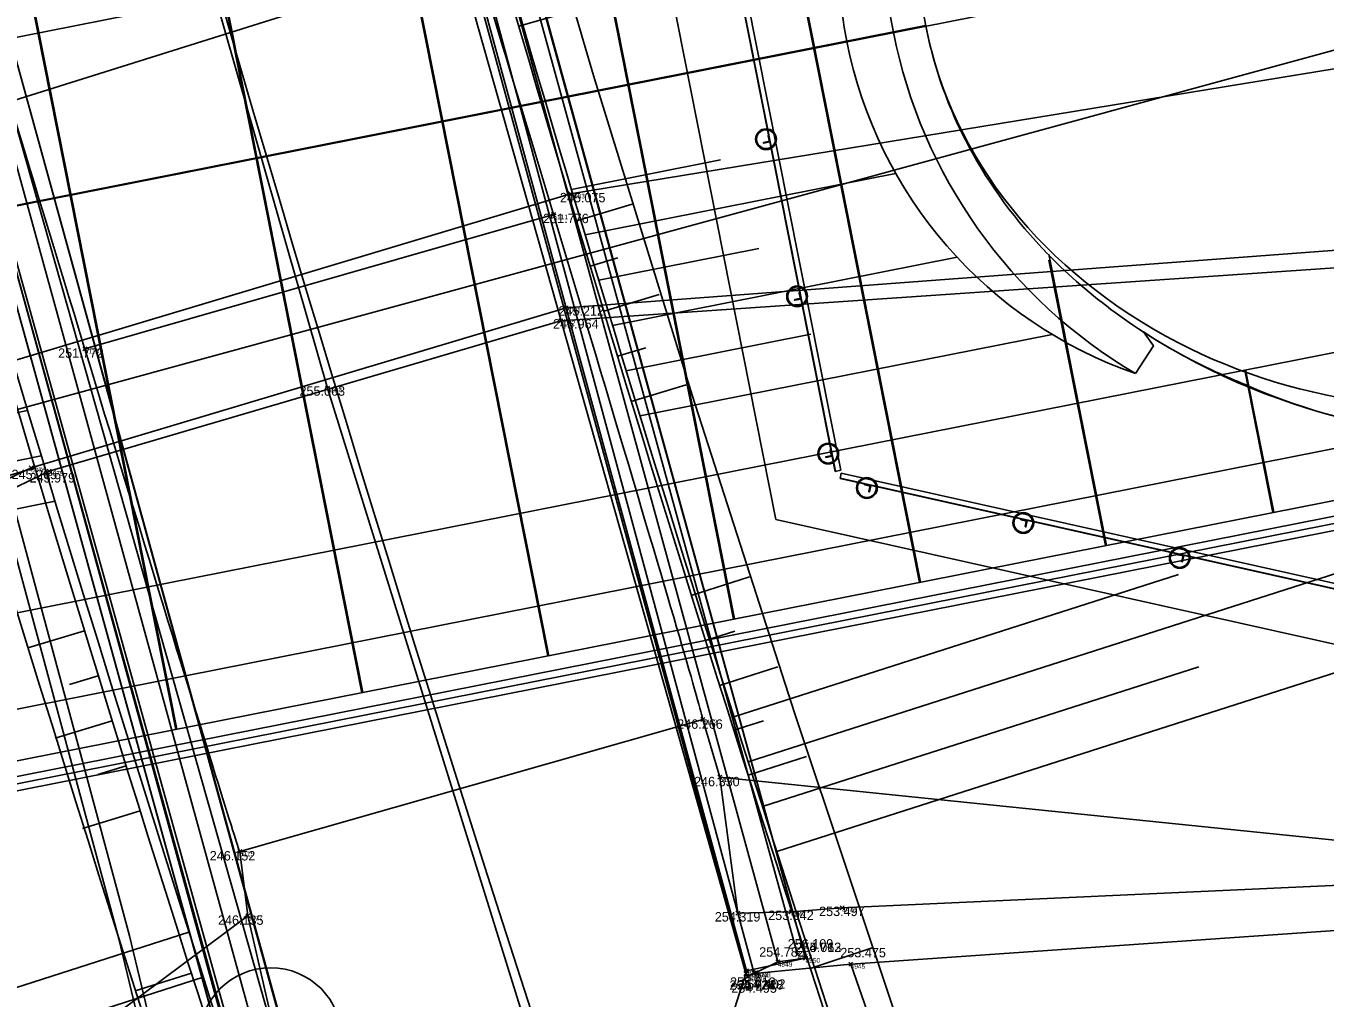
# Model space of a CAD drawing. Extents: x -809973 to -809318, y -1011363 to -1010505.
# Drawn here: x -809841.74 to -809827.96, y -1010996.1 to -1010985.79 of the extents above; entities that cross this region are included whole.
import ezdxf

# ---------------------------------------------------------------- set-up
doc = ezdxf.new("R2010")
doc.units = 0
for name, color, linetype in [('18b - zaměření - čísla bodů', 7, 'Continuous'), ('18c - zaměření - výšky', 7, 'Continuous'), ('21 - sítě', 7, 'Continuous'), ('21a - sítě - DKK - ČD Telematika a.s.', 7, 'Continuous'), ('21b - sítě - SŽDC - SSZT', 7, 'Continuous'), ('21d - sítě - obnova rybníku a obnova náhonu pro rybník', 7, 'Continuous'), ('Návrh', 7, 'Continuous'), ('SO04 - Železniční spodek', 7, 'Continuous'), ('SO05 - Úprava kabelů', 7, 'Continuous'), ('SO_01', 7, 'Continuous'), ('stav_stav', 7, 'Continuous')]:
    doc.layers.add(name, color=color, linetype=linetype)

# ---------------------------------------------------------------- blocks, each defined once
blk = doc.blocks.new('POINT_DISPLAY')
for p, q in [((-0.021, -0.021), (0.021, 0.021)), ((-0.021, 0.021), (0.021, -0.021))]:
    blk.add_line(p, q)

msp = doc.modelspace()

# ---------------------------------------------------------------- linework, layer by layer
at = {"layer": '21 - sítě'}
msp.add_lwpolyline([(-809832.875, -1011017.263), (-809833.494, -1011015.746), (-809838.391, -1011005.426), (-809840.703, -1011001.729), (-809840.806, -1011000.123), (-809839.446, -1010997.434), (-809844.081, -1010980.644), (-809845.074, -1010978.711), (-809846.471, -1010977.412)], dxfattribs=at)
at = {"layer": '21a - sítě - DKK - ČD Telematika a.s.'}
msp.add_lwpolyline([(-809840.802, -1011000.183), (-809839.446, -1010997.434), (-809844.081, -1010980.644), (-809845.074, -1010978.711), (-809846.471, -1010977.412)], dxfattribs=at)
at = {"layer": '21b - sítě - SŽDC - SSZT'}
msp.add_lwpolyline([(-809840.802, -1011000.183), (-809839.446, -1010997.434), (-809844.081, -1010980.644), (-809845.074, -1010978.711), (-809846.471, -1010977.412)], dxfattribs=at)
at = {"layer": '21d - sítě - obnova rybníku a obnova náhonu pro rybník'}
msp.add_lwpolyline([(-809884.652, -1011011.671), (-809852.391, -1010992.741), (-809838.71, -1010989.006), (-809826.649, -1010985.714), (-809807.016, -1010985.926), (-809784.688, -1010978.607)], dxfattribs=at)
at = {"layer": 'Návrh'}
msp.add_arc((-809483.868, -1010882.207), 370.5, 195.00213, 204.78693, dxfattribs=at)
at = {"layer": 'SO04 - Železniční spodek'}
for points in [[(-809844.502, -1010948.259), (-809843.86, -1010951.753), (-809843.202, -1010955.243), (-809842.522, -1010958.729), (-809841.813, -1010962.21), (-809841.069, -1010965.683), (-809840.285, -1010969.148), (-809839.459, -1010972.604), (-809838.59, -1010976.05), (-809837.678, -1010979.484), (-809836.721, -1010982.905), (-809835.72, -1010986.314), (-809834.673, -1010989.708), (-809833.585, -1010993.088), (-809832.46, -1010996.457), (-809831.306, -1010999.816), (-809830.127, -1011003.167), (-809828.93, -1011006.512), (-809827.721, -1011009.854), (-809826.507, -1011013.193)], [(-809835.954, -1010985.634), (-809836.514, -1010985.793)], [(-809835.312, -1010987.682), (-809835.9, -1010987.859)], [(-809835.461, -1010988.249), (-809835.756, -1010988.338)], [(-809835.025, -1010988.64), (-809835.611, -1010988.816)], [(-809835.167, -1010989.205), (-809835.466, -1010989.295)], [(-809834.739, -1010989.598), (-809835.32, -1010989.773)], [(-809842.264, -1010990.66), (-809841.644, -1010990.478)], [(-809834.065, -1010991.635), (-809834.683, -1010991.832)], [(-809841.721, -1010992.389), (-809841.12, -1010992.207)], [(-809834.222, -1010992.21), (-809834.533, -1010992.309)], [(-809833.764, -1010992.589), (-809834.383, -1010992.786)], [(-809841.278, -1010992.778), (-809840.973, -1010992.685)], [(-809841.431, -1010993.346), (-809840.826, -1010993.163)], [(-809833.918, -1010993.163), (-809834.232, -1010993.263)], [(-809833.462, -1010993.542), (-809834.081, -1010993.739)], [(-809840.978, -1010993.732), (-809840.678, -1010993.641)], [(-809841.141, -1010994.304), (-809840.529, -1010994.118)], [(-809832.765, -1010995.572), (-809833.421, -1010995.79)], [(-809840.582, -1010996.028), (-809839.985, -1010995.841)]]:
    msp.add_lwpolyline(points, dxfattribs=at)
for centre, radius, start, end in [((-809453.305, -1010872.818), 406.4, 193.63597, 201.43276), ((-809483.922, -1010882.181), 367.5, 195.00277, 200.92799), ((-809524.411, -1010895.31), 331.2, 194.62152, 202.36706)]:
    msp.add_arc(centre, radius, start, end, dxfattribs=at)
at = {"layer": 'SO05 - Úprava kabelů'}
for points in [[(-809832.452, -1011018.3), (-809834.599, -1011012.541), (-809836.558, -1011007.657), (-809839.63, -1011000.177), (-809840.754, -1010995.474), (-809845.885, -1010976.431), (-809847.466, -1010970.457), (-809849.998, -1010958.97), (-809853.746, -1010939.574), (-809862.448, -1010886.367), (-809861.681, -1010881.903), (-809870.184, -1010824.906)], [(-809832.343, -1011018.259), (-809834.49, -1011012.499), (-809836.45, -1011007.613), (-809839.519, -1011000.141), (-809840.641, -1010995.445), (-809845.773, -1010976.401), (-809847.353, -1010970.429), (-809849.884, -1010958.947), (-809853.631, -1010939.554), (-809862.33, -1010886.367), (-809861.563, -1010881.905), (-809870.069, -1010824.889)]]:
    msp.add_lwpolyline(points, dxfattribs=at)
at = {"layer": 'SO_01'}
for p, q in [((-809834.505, -1010980.356), (-809832.262, -1010991.694)), ((-809834.495, -1010980.354), (-809832.252, -1010991.692)), ((-809836.477, -1010980.746), (-809834.234, -1010992.084)), ((-809836.467, -1010980.744), (-809834.224, -1010992.082)), ((-809838.448, -1010981.136), (-809836.206, -1010992.474)), ((-809838.439, -1010981.134), (-809836.196, -1010992.472)), ((-809840.42, -1010981.526), (-809838.178, -1010992.864)), ((-809840.41, -1010981.524), (-809838.168, -1010992.862)), ((-809833.153, -1010990.515), (-809834.88, -1010981.784)), ((-809833.099, -1010990.504), (-809834.826, -1010981.774)), ((-809842.392, -1010981.916), (-809840.149, -1010993.254)), ((-809842.382, -1010981.914), (-809840.14, -1010993.252)), ((-809833.158, -1010990.516), (-809834.885, -1010981.785)), ((-809830.791, -1010985.512), (-809846.92, -1010988.702)), ((-809832.198, -1010985.784), (-809846.393, -1010988.591)), ((-809835.954, -1010987.524), (-809834.372, -1010987.211)), ((-809835.81, -1010988.005), (-809832.516, -1010987.354)), ((-809835.665, -1010988.486), (-809833.967, -1010988.15)), ((-809835.519, -1010988.967), (-809831.864, -1010988.244)), ((-809830.892, -1010988.212), (-809830.281, -1010991.302)), ((-809830.89, -1010988.274), (-809830.29, -1010991.304)), ((-809825.262, -1010988.739), (-809851.681, -1010993.965)), ((-809835.373, -1010989.448), (-809833.417, -1010989.061)), ((-809835.226, -1010989.928), (-809830.855, -1010989.064)), ((-809828.515, -1010990.952), (-809828.814, -1010989.442)), ((-809828.505, -1010990.95), (-809828.804, -1010989.44)), ((-809825.951, -1010989.895), (-809851.487, -1010994.946)), ((-809841.723, -1010989.871), (-809843.735, -1010990.269)), ((-809824.964, -1010990.25), (-809851.382, -1010995.475)), ((-809841.578, -1010990.352), (-809845.847, -1010991.197)), ((-809834.081, -1010993.596), (-809824.691, -1010990.588)), ((-809833.158, -1010990.516), (-809833.099, -1010990.504)), ((-809833.093, -1010990.534), (-809833.106, -1010990.592)), ((-809825.884, -1010992.206), (-809833.106, -1010990.592)), ((-809825.883, -1010992.202), (-809833.105, -1010990.588)), ((-809825.871, -1010992.148), (-809833.093, -1010990.534)), ((-809841.432, -1010990.833), (-809843.835, -1010991.308)), ((-809827.49, -1010990.916), (-809849.805, -1010995.33)), ((-809827.475, -1010990.99), (-809849.791, -1010995.404)), ((-809827.46, -1010991.063), (-809849.776, -1010995.477)), ((-809834.232, -1010993.119), (-809829.517, -1010991.609)), ((-809833.776, -1010994.548), (-809824.572, -1010991.6)), ((-809833.929, -1010994.072), (-809829.301, -1010992.59)), ((-809840.011, -1010995.405), (-809845.671, -1010997.224)), ((-809839.859, -1010995.881), (-809851.084, -1010999.488))]:
    msp.add_line(p, q, dxfattribs=at)
for points in [[(-809824.741, -1010990.164), (-809824.472, -1010992.461), (-809826.009, -1010992.763), (-809833.786, -1010991.025), (-809835.659, -1010981.554)], [(-809854.161, -1010988.344), (-809830.022, -1010983.57)], [(-809833.919, -1010987.03), (-809833.918, -1010987.032), (-809833.849, -1010987.019)], [(-809833.867, -1010987.015), (-809833.915, -1010987.025)], [(-809833.869, -1010986.956), (-809833.859, -1010987.005)], [(-809833.849, -1010987.019), (-809833.863, -1010986.95), (-809833.866, -1010986.951)], [(-809833.539, -1010988.624), (-809833.53, -1010988.672)], [(-809833.52, -1010988.687), (-809833.533, -1010988.618), (-809833.536, -1010988.618)], [(-809833.589, -1010988.698), (-809833.588, -1010988.7), (-809833.52, -1010988.687)], [(-809833.537, -1010988.683), (-809833.585, -1010988.692)], [(-809829.972, -1010989.478), (-809829.782, -1010989.184), (-809829.887, -1010989.036)], [(-809833.209, -1010990.291), (-809833.2, -1010990.34)], [(-809833.19, -1010990.354), (-809833.203, -1010990.286), (-809833.206, -1010990.286)], [(-809833.259, -1010990.365), (-809833.258, -1010990.368), (-809833.19, -1010990.354)], [(-809833.207, -1010990.351), (-809833.255, -1010990.36)], [(-809832.779, -1010990.666), (-809832.848, -1010990.65), (-809832.848, -1010990.653)], [(-809832.845, -1010990.658), (-809832.796, -1010990.669)], [(-809832.79, -1010990.68), (-809832.8, -1010990.728)], [(-809832.797, -1010990.733), (-809832.794, -1010990.734), (-809832.779, -1010990.666)], [(-809831.12, -1010991.036), (-809831.188, -1010991.021), (-809831.189, -1010991.023)], [(-809831.186, -1010991.029), (-809831.137, -1010991.04)], [(-809831.13, -1010991.05), (-809831.141, -1010991.099)], [(-809831.138, -1010991.104), (-809831.135, -1010991.105), (-809831.12, -1010991.036)], [(-809829.461, -1010991.407), (-809829.529, -1010991.392), (-809829.53, -1010991.394)], [(-809829.526, -1010991.4), (-809829.478, -1010991.41)], [(-809829.471, -1010991.421), (-809829.482, -1010991.469)], [(-809829.479, -1010991.475), (-809829.476, -1010991.475), (-809829.461, -1010991.407)]]:
    msp.add_lwpolyline(points, dxfattribs=at)
for centre, radius in [((-809833.891, -1010986.991), 0.11), ((-809833.891, -1010986.991), 0.1), ((-809833.561, -1010988.659), 0.11), ((-809833.561, -1010988.659), 0.1), ((-809833.231, -1010990.327), 0.11), ((-809833.231, -1010990.327), 0.1), ((-809832.821, -1010990.692), 0.11), ((-809832.821, -1010990.692), 0.1), ((-809831.162, -1010991.063), 0.11), ((-809831.162, -1010991.063), 0.1), ((-809829.503, -1010991.434), 0.11), ((-809829.503, -1010991.434), 0.1)]:
    msp.add_circle(centre, radius, dxfattribs=at)
for centre, radius, start, end in [((-809483.868, -1010882.207), 367.5, 195.00213, 200.05975), ((-809483.868, -1010882.207), 373.7, 195.00213, 199.87467), ((-809828.427, -1010985.044), 4.696, 131.5786, 250.7932), ((-809827.218, -1010984.804), 5.425, 142.8795, 239.4973), ((-809833.865, -1010986.955), 0.0045, 101.1885, 191.1886), ((-809833.868, -1010987.006), 0.009, 281.1885, 11.1886), ((-809833.914, -1010987.029), 0.0045, 101.1885, 191.1886), ((-809833.535, -1010988.623), 0.0045, 101.1885, 191.1886), ((-809833.538, -1010988.674), 0.009, 281.1885, 11.1886), ((-809833.584, -1010988.697), 0.0045, 101.1885, 191.1886), ((-809826.126, -1010983.238), 6.911, 237.0243, 279.3601), ((-809833.205, -1010990.291), 0.0045, 101.1885, 191.1886), ((-809833.254, -1010990.365), 0.0045, 101.1885, 191.1886), ((-809833.209, -1010990.342), 0.009, 281.1885, 11.1886), ((-809832.844, -1010990.654), 0.0045, 167.4024, 257.4024), ((-809832.796, -1010990.729), 0.0045, 167.4024, 257.4024), ((-809832.798, -1010990.678), 0.009, 347.4024, 77.4024), ((-809831.185, -1010991.024), 0.0045, 167.4024, 257.4024), ((-809831.137, -1010991.1), 0.0045, 167.4024, 257.4024), ((-809831.139, -1010991.048), 0.009, 347.4024, 77.4024), ((-809829.526, -1010991.395), 0.0045, 167.4024, 257.4024), ((-809829.48, -1010991.419), 0.009, 347.4024, 77.4024), ((-809829.478, -1010991.47), 0.0045, 167.4024, 257.4024)]:
    msp.add_arc(centre, radius, start, end, dxfattribs=at)
for centre, major_axis, ratio, start_param, end_param in [((-809825.575, -1010984.48), (-6.622, -1.31), 0.8, 5.497787, 6.283185), ((-809825.575, -1010984.48), (-6.622, -1.31), 0.8, 0, 0.785398), ((-809825.207, -1010984.407), (-6.99, -1.383), 0.800068, 0.000039, 0.478429), ((-809825.207, -1010984.407), (-6.99, -1.383), 0.8, 0.481469, 0.785398), ((-809825.976, -1010984.956), (-5.947, -1.176), 0.8, 0.785398, 1.56521), ((-809825.608, -1010984.883), (-6.315, -1.249), 0.8, 0.785398, 0.894584), ((-809825.979, -1010984.957), (-5.722, -1.132), 0.882873, 0.896781, 1.249758)]:
    msp.add_ellipse(centre, major_axis=major_axis, ratio=ratio, start_param=start_param, end_param=end_param, dxfattribs=at)
at = {"layer": 'stav_stav'}
for p, q in [((-809837.954, -1010979.399), (-809833.471, -1010995.68)), ((-809833.765, -1010995.721), (-809838.217, -1010979.445)), ((-809833.556, -1010995.643), (-809838.001, -1010979.464)), ((-809833.471, -1010995.68), (-809837.949, -1010979.444)), ((-809834.105, -1010995.845), (-809838.678, -1010979.669)), ((-809838.678, -1010979.669), (-809834.105, -1010995.845)), ((-809834.105, -1010995.845), (-809838.547, -1010979.594)), ((-809838.503, -1010979.604), (-809834.099, -1010995.814)), ((-809834.189, -1010995.204), (-809838.271, -1010980.078)), ((-809838.541, -1010989.632), (-809841.189, -1010980.417)), ((-809839.446, -1010997.434), (-809844.081, -1010980.644)), ((-809839.075, -1010997.329), (-809843.582, -1010980.945)), ((-809838.806, -1010997.169), (-809843.283, -1010980.934)), ((-809838.806, -1010997.207), (-809843.283, -1010980.934)), ((-809838.806, -1010997.207), (-809843.283, -1010980.934)), ((-809839.345, -1010997.42), (-809843.876, -1010981.071)), ((-809839.358, -1010997.434), (-809843.865, -1010981.05)), ((-809843.358, -1010981.51), (-809839.041, -1010996.735)), ((-809846.095, -1010987.906), (-809837.047, -1010985.065)), ((-809839.322, -1010997.364), (-809842.539, -1010985.783)), ((-809835.966, -1010987.57), (-809827.372, -1010986.165)), ((-809844.992, -1010990.276), (-809835.966, -1010987.57)), ((-809841.117, -1010989.215), (-809836.145, -1010987.791)), ((-809823.915, -1010987.873), (-809836.01, -1010988.78)), ((-809836.067, -1010988.917), (-809823.939, -1010988.086)), ((-809836.01, -1010988.78), (-809841.685, -1010990.477)), ((-809841.495, -1010990.513), (-809836.067, -1010988.917)), ((-809836.415, -1010996.462), (-809838.541, -1010989.632)), ((-809848.524, -1010993.918), (-809841.495, -1010990.513)), ((-809841.685, -1010990.477), (-809848.428, -1010993.714)), ((-809839.473, -1010994.549), (-809834.561, -1010993.15)), ((-809834.382, -1010993.76), (-809834.561, -1010993.15)), ((-809824.64, -1010994.76), (-809834.382, -1010993.76)), ((-809834.189, -1010995.204), (-809834.382, -1010993.76)), ((-809839.386, -1010995.232), (-809839.473, -1010994.549)), ((-809824.64, -1010994.76), (-809833.083, -1010995.146)), ((-809833.083, -1010995.146), (-809833.623, -1010995.188)), ((-809847.756, -1011001.46), (-809839.386, -1010995.232)), ((-809839.041, -1010996.735), (-809839.386, -1010995.232)), ((-809833.623, -1010995.188), (-809834.189, -1010995.204)), ((-809834.017, -1010995.842), (-809834.189, -1010995.204)), ((-809832.993, -1010995.743), (-809824.518, -1010995.159)), ((-809824.518, -1010995.159), (-809832.993, -1010995.743)), ((-809834.099, -1010995.814), (-809833.471, -1010995.68)), ((-809833.765, -1010995.721), (-809833.471, -1010995.68)), ((-809833.471, -1010995.68), (-809833.471, -1010995.68)), ((-809834.105, -1010995.845), (-809834.099, -1010995.814)), ((-809834.017, -1010995.842), (-809832.993, -1010995.743)), ((-809832.993, -1010995.743), (-809834.017, -1010995.842)), ((-809834.017, -1010995.842), (-809833.995, -1010995.834)), ((-809833.995, -1010995.834), (-809833.765, -1010995.721)), ((-809826.372, -1011014.673), (-809832.993, -1010995.743)), ((-809826.372, -1011014.673), (-809832.993, -1010995.743)), ((-809834.342, -1010996.578), (-809834.105, -1010995.845)), ((-809834.085, -1010995.877), (-809834.105, -1010995.845)), ((-809834.105, -1010995.845), (-809834.085, -1010995.877)), ((-809834.017, -1010995.842), (-809834.085, -1010995.877)), ((-809834.085, -1010995.877), (-809834.017, -1010995.842))]:
    msp.add_line(p, q, dxfattribs=at)
msp.add_circle((-809839.145, -1010996.539), 0.756, dxfattribs=at)
for centre, major_axis, ratio, start_param, end_param in [((-809836.165, -1010987.823), (-1.604, 5.327), 0.005158, 3.151232, 6.385341), ((-809841.093, -1010989.234), (-1.62, 5.315), 0.003059, 6.189212, 9.436189)]:
    msp.add_ellipse(centre, major_axis=major_axis, ratio=ratio, start_param=start_param, end_param=end_param, dxfattribs=at)

# ---------------------------------------------------------------- block references
at = {"layer": '18b - zaměření - čísla bodů'}
for p in [(-809835.966, -1010987.57), (-809836.145, -1010987.791), (-809836.01, -1010988.78), (-809836.067, -1010988.917), (-809841.117, -1010989.215), (-809838.541, -1010989.632), (-809841.685, -1010990.477), (-809841.495, -1010990.513), (-809834.561, -1010993.15), (-809834.382, -1010993.76), (-809839.473, -1010994.549), (-809833.083, -1010995.146), (-809839.386, -1010995.232), (-809834.189, -1010995.204), (-809833.623, -1010995.188), (-809833.765, -1010995.721), (-809833.556, -1010995.643), (-809833.471, -1010995.68), (-809833.471, -1010995.68), (-809834.105, -1010995.845), (-809834.099, -1010995.814), (-809834.017, -1010995.842), (-809833.995, -1010995.834), (-809832.993, -1010995.743), (-809834.085, -1010995.877)]:
    msp.add_blockref('POINT_DISPLAY', p, dxfattribs=at)

# ---------------------------------------------------------------- texts
for s, p in [('5083', (-809835.966, -1010987.62)), ('5111', (-809836.145, -1010987.841)), ('5081', (-809836.01, -1010988.83)), ('5082', (-809836.067, -1010988.967)), ('5114', (-809841.117, -1010989.265)), ('4904', (-809838.541, -1010989.682)), ('5076', (-809841.685, -1010990.527)), ('5075', (-809841.495, -1010990.563)), ('5112', (-809834.561, -1010993.2)), ('5110', (-809834.382, -1010993.81)), ('5115', (-809839.473, -1010994.599)), ('4946', (-809833.083, -1010995.196)), ('5077', (-809839.386, -1010995.282)), ('5', (-809834.189, -1010995.254)), ('4947', (-809833.623, -1010995.238)), ('4952', (-809833.556, -1010995.693)), ('4950', (-809833.471, -1010995.73)), ('3', (-809833.471, -1010995.73)), ('4951', (-809834.099, -1010995.864)), ('4948', (-809833.995, -1010995.884)), ('4949', (-809833.765, -1010995.771)), ('4945', (-809832.993, -1010995.793)), ('4942', (-809834.105, -1010995.895)), ('4943', (-809834.085, -1010995.927)), ('4944', (-809834.017, -1010995.892))]:
    msp.add_text(s, height=0.05, dxfattribs=at).set_placement(p)
at = {"layer": '18c - zaměření - výšky'}
for s, p in [('245.075', (-809836.077, -1010987.661)), ('251.776', (-809836.255, -1010987.882)), ('245.212', (-809836.093, -1010988.864)), ('245.964', (-809836.15, -1010989.001)), ('251.772', (-809841.399, -1010989.311)), ('255.063', (-809838.839, -1010989.713)), ('245.265', (-809841.893, -1010990.598)), ('245.979', (-809841.702, -1010990.634)), ('246.266', (-809834.833, -1010993.247)), ('246.330', (-809834.654, -1010993.857)), ('246.152', (-809839.791, -1010994.644)), ('253.497', (-809833.328, -1010995.234)), ('246.135', (-809839.704, -1010995.327)), ('254.319', (-809834.434, -1010995.292)), ('253.942', (-809833.868, -1010995.276)), ('256.109', (-809833.661, -1010995.579)), ('254.763', (-809833.576, -1010995.616)), ('255.012', (-809833.576, -1010995.616)), ('254.782', (-809833.963, -1010995.665)), ('253.475', (-809833.103, -1010995.672)), ('254.724', (-809834.278, -1010996.016)), ('255.012', (-809834.272, -1010995.985)), ('254.495', (-809834.259, -1010996.048)), ('254.328', (-809834.19, -1010996.013)), ('254.402', (-809834.168, -1010996.005))]:
    msp.add_text(s, height=0.1, dxfattribs=at).set_placement(p)

doc.saveas('drawing.dxf')
